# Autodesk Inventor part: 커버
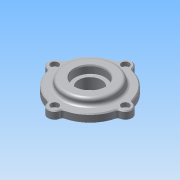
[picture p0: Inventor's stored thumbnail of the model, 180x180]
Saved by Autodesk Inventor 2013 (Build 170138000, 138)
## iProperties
Company: 한국ATC센터
Created: 2015-12
Part Number: 커버
Document SubType Name: Modeling
Designer: mdu
Density: 2.71 g/cm^3
Material: 알루미늄 6061
Mass: 135.241 g
Surface Area: 145.431 cm^2
Volume: 49.9044 cm^3
Author: mdu
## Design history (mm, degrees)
sketch "스케치1"
  geometry: C1 r 1.621 at (0, 6.75) reference; C2 r 1.621 at (-37, -30.25) reference; C3 r 1.621 at (0, -67.25) reference; C4 r 1.621 at (37, -30.25) reference; C5 r 10 at (0, -30.25) reference; C6 r 12 at (0, -30.25); C7 r 24.5 at (0, -30.25) reference; A1 r 3 centre (-38.77, -20.408) between (-38.239, -23.361) and (-35.862, -21.146) reference; A2 r 7 centre (-37, -30.25) between (-38.239, -23.361) and (-38.239, -37.139) reference; A3 r 3 centre (-38.77, -40.092) between (-35.862, -39.354) and (-38.239, -37.139) reference; A4 r 37 centre (0, -30.25) between (-35.862, -39.354) and (-9.104, -66.113) reference; A5 r 3 centre (-9.842, -69.02) between (-6.889, -68.489) and (-9.104, -66.113) reference; A6 r 7 centre (0, -67.25) between (-6.889, -68.489) and (6.889, -68.489) reference; A7 r 3 centre (9.842, -69.02) between (9.104, -66.112) and (6.889, -68.489) reference; A8 r 37 centre (0, -30.25) between (9.104, -66.112) and (35.863, -39.354) reference; A9 r 3 centre (38.77, -40.092) between (38.239, -37.139) and (35.863, -39.354) reference; A10 r 7 centre (37, -30.25) between (38.239, -37.139) and (38.239, -23.361) reference; A11 r 3 centre (38.77, -20.408) between (35.863, -21.146) and (38.239, -23.361) reference; A12 r 37 centre (0, -30.25) between (35.863, -21.146) and (9.104, 5.612) reference; A13 r 3 centre (9.842, 8.52) between (6.889, 7.989) and (9.104, 5.612) reference; A14 r 7 centre (0, 6.75) between (6.889, 7.989) and (-6.889, 7.989) reference; A15 r 3 centre (-9.842, 8.52) between (-9.104, 5.612) and (-6.889, 7.989) reference; A16 r 37 centre (0, -30.25) between (-9.104, 5.612) and (-35.862, -21.146) reference; 1 further point
  constraints: 1 centre point, 1 coincident
  dimensions: "d2" = 2 radial gap between concentric circles of C6 C5
extrude "돌출1" new body sketch "스케치1" distance "d0" = 8; taper "d1" = 0 deg
sketch "스케치2"
  geometry: C1 r 23.5 at (0, -30.25) reference; C2 r 12 at (0, -30.25) reference; 1 further point
extrude "돌출2" join sketch "스케치2" distance "d4" = 5; taper "d5" = 0 deg
sketch "스케치3"
  geometry: C1 r 23.5 at (0, 0) reference; C2 r 20.5 at (0, 0); 1 further point
  constraints: 1 centre point
  dimensions: "d6" = 3 radial gap between concentric circles of C2 C1
node "작업 평면1"
extrude "돌출3" join sketch "스케치3" stored distance "d7" = 5; taper "d8" = 0 deg
fillet "모깎기1" dims "d9" = 3
sketch "스케치4"
  geometry: C1 r 12 at (0, -30.25) reference; C2 r 27 at (0, -30.25); 1 further point
  constraints: 1 centre point
  dimensions: "d10" = 15 radial gap between concentric circles of C1 C2
extrude "돌출4" join sketch "스케치4" distance "d11" = 7; taper "d12" = 0 deg
fillet "모깎기2" dims "d13" = 3
chamfer "모따기1" distance "d14" = 1; stored, may be unused: second distance "d15" = 2, angle "d16" = 45 deg
node "작업점1"
  node "작업축1"
chamfer "모따기2" distance "d24" = 1; stored, may be unused: second distance "d25" = 2, angle "d26" = 45 deg
hole "구멍6" diameter "d43" = 4.5; stored, may be unused: countersink angle "d47" = 90 deg, drill point angle "d49" = 118 deg; dims "d41" = 10, "d42" = 10, "d44" = 6, "d45" = 8, "d46" = 4.4, "d48" = 8
sketch "스케치8"
  geometry: C1 r 12 at (0, 0) reference; C2 r 16 at (0, 0); 1 further point
  constraints: 1 centre point, 1 coincident
  dimensions: "d53" = 32 diameter of C2
extrude "돌출5" cut sketch "스케치8" distance "d54" = 8.3; taper "d55" = 0 deg
fillet "모깎기3" dims "d56" = 0.3
chamfer "모따기3" distance "d57" = 1.2; stored, may be unused: second distance "d58" = 2, angle "d59" = 30 deg
node "솔리드1"
pattern_circular "원형 패턴1" dims angle "d51" = 360 deg
node "참조1"
node "참조2"
